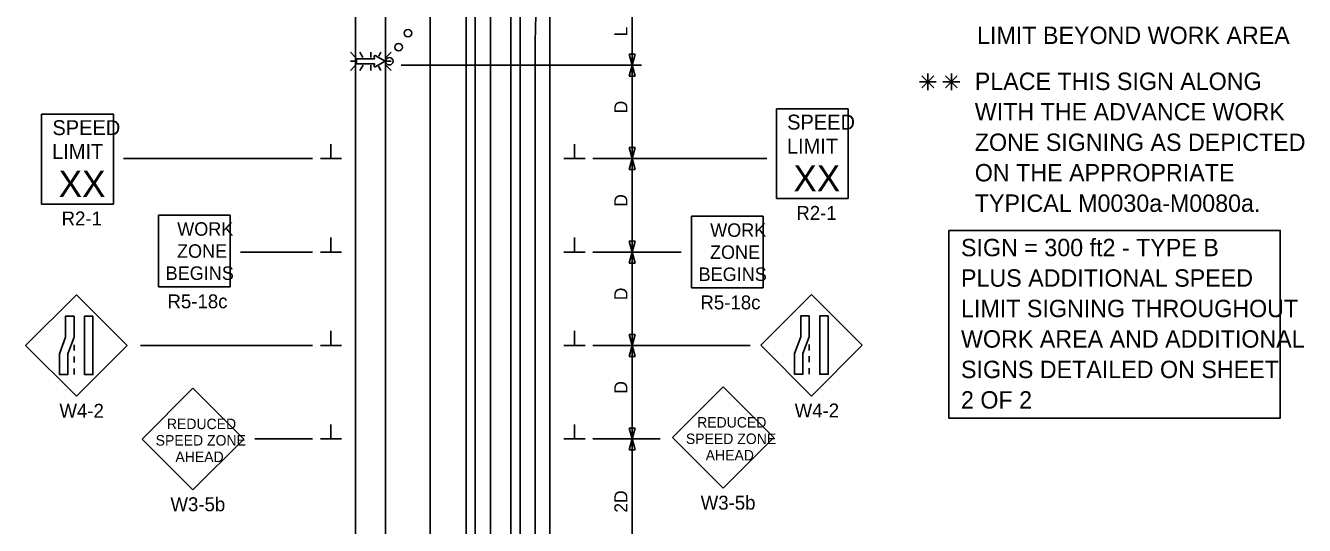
# Model space of a CAD drawing. Extents: x 16731 to 18464, y 5737 to 6974.
# Drawn here: x 16745 to 17429, y 6268 to 6535 of the extents above; entities that cross this region are included whole.
import ezdxf

# ---------------------------------------------------------------- set-up
doc = ezdxf.new("R2010")
doc.units = 0
for name, color, linetype in [('ALI_LEGAL_EX', 7, 'Continuous'), ('PAVT_EDGE_EX', 7, 'Continuous'), ('TRAFFIC_SIGNS_PR', 7, 'Continuous'), ('TYPICAL_TEXT_DIMEN_EX', 7, 'Continuous'), ('TYPICAL_TEXT_DIMEN_PR', 7, 'Continuous')]:
    doc.layers.add(name, color=color, linetype=linetype)

msp = doc.modelspace()

# ---------------------------------------------------------------- linework, layer by layer
at = {"layer": 'ALI_LEGAL_EX'}
for p, q in [((16980.68, 6974.12), (16980.68, 6155.98)), ((17004.68, 6974.12), (17004.68, 6155.98)), ((16980.68, 6891.53), (16980.68, 6027.61)), ((17004.68, 6891.53), (17004.68, 6027.61)), ((16961.51, 6069.17), (16961.51, 6569.52)), ((16985.51, 6054.68), (16985.51, 6555.03)), ((16993.65, 6039.29), (16993.65, 6539.64)), ((17017.65, 6024.8), (17017.65, 6525.15))]:
    msp.add_line(p, q, dxfattribs=at)
for points in [[(16961.51, 6469.17), (16961.51, 6494.17)], [(16985.51, 6469.17), (16985.51, 6494.17)], [(16961.51, 6369.17), (16961.51, 6394.17)], [(16985.51, 6369.17), (16985.51, 6394.17)], [(16961.51, 6269.17), (16961.51, 6294.17)], [(16985.51, 6269.17), (16985.51, 6294.17)]]:
    msp.add_lwpolyline(points, dxfattribs=at)
msp.add_arc((17357.65, 6525.15), 340, 129.56655, 180, dxfattribs=at)
at = {"layer": 'PAVT_EDGE_EX'}
for p, q in [((16921.51, 6569.52), (16921.51, 6043.9)), ((16937.51, 6569.52), (16937.51, 6043.9)), ((17009.51, 6569.52), (17009.51, 6043.9)), ((17025.51, 6569.52), (17025.51, 6043.9))]:
    msp.add_line(p, q, dxfattribs=at)
at = {"layer": 'TRAFFIC_SIGNS_PR'}
for p, q in [((16921.58, 6517.92), (16918.76, 6520.74)), ((16923.88, 6520.74), (16925.51, 6517.92)), ((16929.67, 6517.92), (16929.67, 6520.74)), ((16935.13, 6520.74), (16933.93, 6518.65)), ((16940.57, 6520.74), (16937.75, 6517.92)), ((16921.58, 6515.89), (16918.76, 6515.89)), ((16921.58, 6513.86), (16918.76, 6511.04)), ((16925.53, 6513.86), (16923.9, 6511.04)), ((16929.67, 6513.86), (16929.67, 6511.04)), ((16933.85, 6513.23), (16935.11, 6511.04)), ((16937.75, 6515.89), (16940.57, 6515.89)), ((16940.57, 6511.04), (16937.75, 6513.86)), ((16753.66, 6487.55), (16792.06, 6487.55)), ((16753.66, 6439.55), (16753.66, 6487.55)), ((16792.06, 6439.55), (16792.06, 6487.55)), ((17146.61, 6490.51), (17185.01, 6490.51)), ((17146.61, 6442.51), (17146.61, 6490.51)), ((17185.01, 6442.51), (17185.01, 6490.51)), ((16753.66, 6439.55), (16792.06, 6439.55)), ((17146.61, 6442.51), (17185.01, 6442.51)), ((16816.16, 6395.22), (16816.16, 6433.62)), ((16816.16, 6433.62), (16854.56, 6433.62)), ((16854.56, 6395.22), (16854.56, 6433.62)), ((17101.21, 6394.64), (17101.21, 6433.04)), ((17101.21, 6433.04), (17139.61, 6433.04)), ((17139.61, 6394.64), (17139.61, 6433.04)), ((16816.16, 6395.22), (16854.56, 6395.22)), ((16772.22, 6390.97), (16745.06, 6363.82)), ((16799.37, 6363.82), (16772.22, 6390.97)), ((17101.21, 6394.64), (17139.61, 6394.64)), ((17165.42, 6391.13), (17138.26, 6363.97)), ((17192.57, 6363.97), (17165.42, 6391.13)), ((16745.06, 6363.82), (16772.22, 6336.67)), ((16770.97, 6364.31), (16770.97, 6361.11)), ((16772.22, 6336.67), (16799.37, 6363.82)), ((17138.26, 6363.97), (17165.42, 6336.82)), ((17164.17, 6364.47), (17164.17, 6361.27)), ((17165.42, 6336.82), (17192.57, 6363.97)), ((16770.97, 6357.91), (16770.97, 6354.71)), ((17164.17, 6358.07), (17164.17, 6354.87)), ((16770.97, 6351.51), (16770.97, 6348.31)), ((17164.17, 6351.67), (17164.17, 6348.47)), ((16834.6, 6340.96), (16807.44, 6313.81)), ((16861.75, 6313.81), (16834.6, 6340.96)), ((17118.18, 6341.8), (17091.03, 6314.65)), ((17145.33, 6314.65), (17118.18, 6341.8)), ((16807.44, 6313.81), (16834.6, 6286.65)), ((16834.6, 6286.65), (16861.75, 6313.81)), ((17091.03, 6314.65), (17118.18, 6287.5)), ((17118.18, 6287.5), (17145.33, 6314.65))]:
    msp.add_line(p, q, dxfattribs=at)
for points in [[(16931.49, 6518.57), (16931.72, 6517.28), (16922, 6517.28), (16922, 6514.53), (16931.72, 6514.53), (16931.49, 6513.23)], [(16931.99, 6512.88), (16937.3, 6515.89), (16931.99, 6518.93)]]:
    msp.add_lwpolyline(points, dxfattribs=at)
for points in [[(16770.97, 6379.56), (16770.97, 6368.38), (16767.63, 6359.49), (16767.63, 6348.31), (16763.13, 6348.31), (16763.13, 6359.49), (16766.48, 6368.38), (16766.48, 6379.56)], [(16781.11, 6379.56), (16781.11, 6348.31), (16776.61, 6348.31), (16776.61, 6379.56)], [(17164.17, 6379.71), (17164.17, 6368.53), (17160.83, 6359.65), (17160.83, 6348.47), (17156.33, 6348.47), (17156.33, 6359.65), (17159.68, 6368.53), (17159.68, 6379.71)], [(17174.31, 6379.71), (17174.31, 6348.47), (17169.81, 6348.47), (17169.81, 6379.71)]]:
    msp.add_lwpolyline(points, close=True, dxfattribs=at)
for centre in [(16949.56, 6530.94), (16944.59, 6523.44), (16939.62, 6515.93)]:
    msp.add_circle(centre, 2, dxfattribs=at)
for centre, start, end in [((16931.83, 6518.63), 61.48329, 189.95933), ((16931.83, 6513.18), 170.73078, 298.89165)]:
    msp.add_arc(centre, 0.341, start, end, dxfattribs=at)
at = {"layer": 'TYPICAL_TEXT_DIMEN_EX'}
msp.add_lwpolyline([(17238.83, 6425.42), (17416.11, 6425.42), (17416.11, 6325.04), (17238.83, 6325.04)], close=True, dxfattribs=at)
at = {"layer": 'TYPICAL_TEXT_DIMEN_PR'}
for p, q in [((17069.51, 6545.96), (17069.51, 6513.85)), ((17069.51, 6513.85), (17067.94, 6519.72)), ((17067.94, 6519.72), (17069.51, 6519.72)), ((17069.51, 6519.72), (17071.08, 6519.72)), ((17071.08, 6519.72), (17069.51, 6513.85)), ((16945.91, 6513.85), (17074.51, 6513.85)), ((17067.94, 6507.99), (17069.51, 6513.85)), ((17069.51, 6513.85), (17069.51, 6463.85)), ((17069.51, 6513.85), (17071.08, 6507.99)), ((17069.51, 6507.99), (17067.94, 6507.99)), ((17071.08, 6507.99), (17069.51, 6507.99)), ((17227.64, 6504.88), (17223.1, 6504.88)), ((17224.45, 6508.07), (17230.82, 6501.69)), ((17230.82, 6508.07), (17224.45, 6501.69)), ((17227.64, 6504.88), (17227.64, 6509.34)), ((17227.64, 6504.88), (17230.82, 6504.88)), ((17227.64, 6504.88), (17232.11, 6504.88)), ((17227.64, 6504.88), (17227.64, 6500.38)), ((17240.19, 6504.88), (17235.66, 6504.88)), ((17237, 6508.07), (17243.38, 6501.69)), ((17243.38, 6508.07), (17237, 6501.69)), ((17240.19, 6504.88), (17240.19, 6509.34)), ((17240.19, 6504.88), (17243.38, 6504.88)), ((17240.19, 6504.88), (17244.67, 6504.88)), ((17240.19, 6504.88), (17240.19, 6500.38)), ((16908.39, 6463.85), (16908.39, 6471.64)), ((17038.64, 6463.85), (17038.64, 6471.64)), ((16797.52, 6463.85), (16898.51, 6463.85)), ((16902.76, 6463.85), (16914.01, 6463.85)), ((17044.26, 6463.85), (17033.01, 6463.85)), ((17048.51, 6463.85), (17141.53, 6463.85)), ((17069.51, 6463.85), (17067.94, 6469.72)), ((17067.94, 6469.72), (17069.51, 6469.72)), ((17067.94, 6457.99), (17069.51, 6463.85)), ((17069.51, 6469.72), (17071.08, 6469.72)), ((17071.08, 6469.72), (17069.51, 6463.85)), ((17069.51, 6463.85), (17069.51, 6413.85)), ((17069.51, 6463.85), (17071.08, 6457.99)), ((17069.51, 6457.99), (17067.94, 6457.99)), ((17071.08, 6457.99), (17069.51, 6457.99)), ((16908.39, 6413.85), (16908.39, 6421.64)), ((17038.64, 6413.85), (17038.64, 6421.64)), ((17069.51, 6413.85), (17067.94, 6419.72)), ((17067.94, 6419.72), (17069.51, 6419.72)), ((17069.51, 6419.72), (17071.08, 6419.72)), ((17071.08, 6419.72), (17069.51, 6413.85)), ((16898.51, 6413.85), (16860.08, 6413.85)), ((16902.76, 6413.85), (16914.01, 6413.85)), ((17044.26, 6413.85), (17033.01, 6413.85)), ((17048.51, 6413.85), (17095.65, 6413.85)), ((17067.94, 6407.99), (17069.51, 6413.85)), ((17069.51, 6413.85), (17069.51, 6363.85)), ((17069.51, 6413.85), (17071.08, 6407.99)), ((17069.51, 6407.99), (17067.94, 6407.99)), ((17071.08, 6407.99), (17069.51, 6407.99)), ((16908.39, 6363.85), (16908.39, 6371.64)), ((17038.64, 6363.85), (17038.64, 6371.64)), ((17069.51, 6363.85), (17067.94, 6369.72)), ((17067.94, 6369.72), (17069.51, 6369.72)), ((17069.51, 6369.72), (17071.08, 6369.72)), ((17071.08, 6369.72), (17069.51, 6363.85)), ((16898.51, 6363.85), (16806.49, 6363.85)), ((16902.76, 6363.85), (16914.01, 6363.85)), ((17044.26, 6363.85), (17033.01, 6363.85)), ((17048.51, 6363.85), (17132.56, 6363.85)), ((17067.94, 6357.99), (17069.51, 6363.85)), ((17069.51, 6363.85), (17069.51, 6313.85)), ((17069.51, 6363.85), (17071.08, 6357.99)), ((17069.51, 6357.99), (17067.94, 6357.99)), ((17071.08, 6357.99), (17069.51, 6357.99)), ((16908.39, 6313.85), (16908.39, 6321.64)), ((17038.64, 6313.85), (17038.64, 6321.64)), ((16867.61, 6313.85), (16898.51, 6313.85)), ((16902.76, 6313.85), (16914.01, 6313.85)), ((17044.26, 6313.85), (17033.01, 6313.85)), ((17048.51, 6313.85), (17084.51, 6313.85)), ((17069.51, 6313.85), (17067.94, 6319.72)), ((17067.94, 6319.72), (17069.51, 6319.72)), ((17067.94, 6307.99), (17069.51, 6313.85)), ((17069.51, 6319.72), (17071.08, 6319.72)), ((17071.08, 6319.72), (17069.51, 6313.85)), ((17069.51, 6313.85), (17069.51, 6238.85)), ((17069.51, 6313.85), (17071.08, 6307.99)), ((17069.51, 6307.99), (17067.94, 6307.99)), ((17071.08, 6307.99), (17069.51, 6307.99))]:
    msp.add_line(p, q, dxfattribs=at)

# ---------------------------------------------------------------- texts
at = {"layer": 'TRAFFIC_SIGNS_PR'}
for s, height, p in [('SPEED', 8, (16759.43, 6476.41)), ('SPEED', 8, (17152.38, 6479.37)), ('LIMIT', 8, (16759.27, 6463.61)), ('LIMIT', 8, (17152.22, 6466.57)), ('XX', 14.031, (16762.77, 6443.31)), ('XX', 14.031, (17155.72, 6446.27)), ('R2-1', 7.44, (17157.29, 6431.07)), ('R2-1', 7.44, (16764.34, 6428.11)), ('WORK', 7.217, (16826.17, 6422.59)), ('WORK', 7.217, (17111.21, 6422)), ('ZONE', 7.217, (16826.05, 6410.78)), ('ZONE', 7.217, (17111.09, 6410.19)), ('BEGINS', 7.217, (16819.98, 6398.97)), ('BEGINS', 7.217, (17105.02, 6398.38)), ('R5-18c', 7.44, (16820.98, 6383.78)), ('R5-18c', 7.44, (17106.02, 6383.2)), ('W4-2', 7.44, (16763.17, 6325.23)), ('W4-2', 7.44, (17156.38, 6325.38)), ('REDUCED', 5.6, (16820.65, 6319.12)), ('REDUCED', 5.6, (17104.24, 6319.96)), ('SPEED ZONE', 5.6, (16814.65, 6310.32)), ('SPEED ZONE', 5.6, (17098.23, 6311.16)), ('AHEAD', 5.6, (16825.21, 6301.52)), ('AHEAD', 5.6, (17108.79, 6302.36)), ('W3-5b', 7.44, (16822.55, 6275.21)), ('W3-5b', 7.44, (17106.13, 6276.06))]:
    msp.add_text(s, height=height, dxfattribs=at).set_placement(p)
at = {"layer": 'TYPICAL_TEXT_DIMEN_EX'}
for s, p in [('LIMIT BEYOND WORK AREA', (17253.95, 6525.17)), ('PLACE THIS SIGN ALONG', (17252.72, 6500.55)), ('WITH THE ADVANCE WORK', (17252.72, 6484.25)), ('ZONE SIGNING AS DEPICTED', (17252.72, 6467.95)), ('ON THE APPROPRIATE', (17252.72, 6451.65)), ('TYPICAL M0030a-M0080a.', (17252.72, 6435.35)), ('SIGN = 300 ft2 - TYPE B', (17245.35, 6411.62)), ('PLUS ADDITIONAL SPEED', (17245.35, 6395.32)), ('LIMIT SIGNING THROUGHOUT', (17245.35, 6379.02)), ('WORK AREA AND ADDITIONAL', (17245.35, 6362.72)), ('SIGNS DETAILED ON SHEET', (17245.35, 6346.42)), ('2 OF 2', (17245.35, 6330.12))]:
    msp.add_text(s, height=9.3, dxfattribs=at).set_placement(p)
at = {"layer": 'TYPICAL_TEXT_DIMEN_PR'}
for s, p in [('L', (17066.95, 6529.26)), ('D', (17066.95, 6488.07)), ('D', (17066.95, 6438.07)), ('D', (17066.95, 6388.07)), ('D', (17066.95, 6338.07)), ('2D', (17066.95, 6274.41))]:
    msp.add_text(s, height=7, rotation=90, dxfattribs=at).set_placement(p)

doc.saveas('drawing.dxf')
